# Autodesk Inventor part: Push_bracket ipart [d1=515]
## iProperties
Shininess: 69.0
Length Units: 11269
Angle Units: 11279
Time Units: 11290
Mass Units: 11283
Length Display Precision: 3
Angle Display Precision: 2
Created: 2001-04
Part Number: Push_bracket ipart [d1=515]
Material: Standard
Document SubType Name: Modellieren
Designer: dl
Density: 1 g/cm^3
Density: 0.0
Volumn: 0.0
Area: 0.0
PropertySet Name: Model Information
Control State: 0
Master: False
Checked Out: False
Author: dl
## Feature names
1. TaggingFeature2
